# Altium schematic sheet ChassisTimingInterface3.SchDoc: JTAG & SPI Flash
size B; DocumentNumber: 4; Revision: C; SheetNumber: 3; SheetTotal: 12
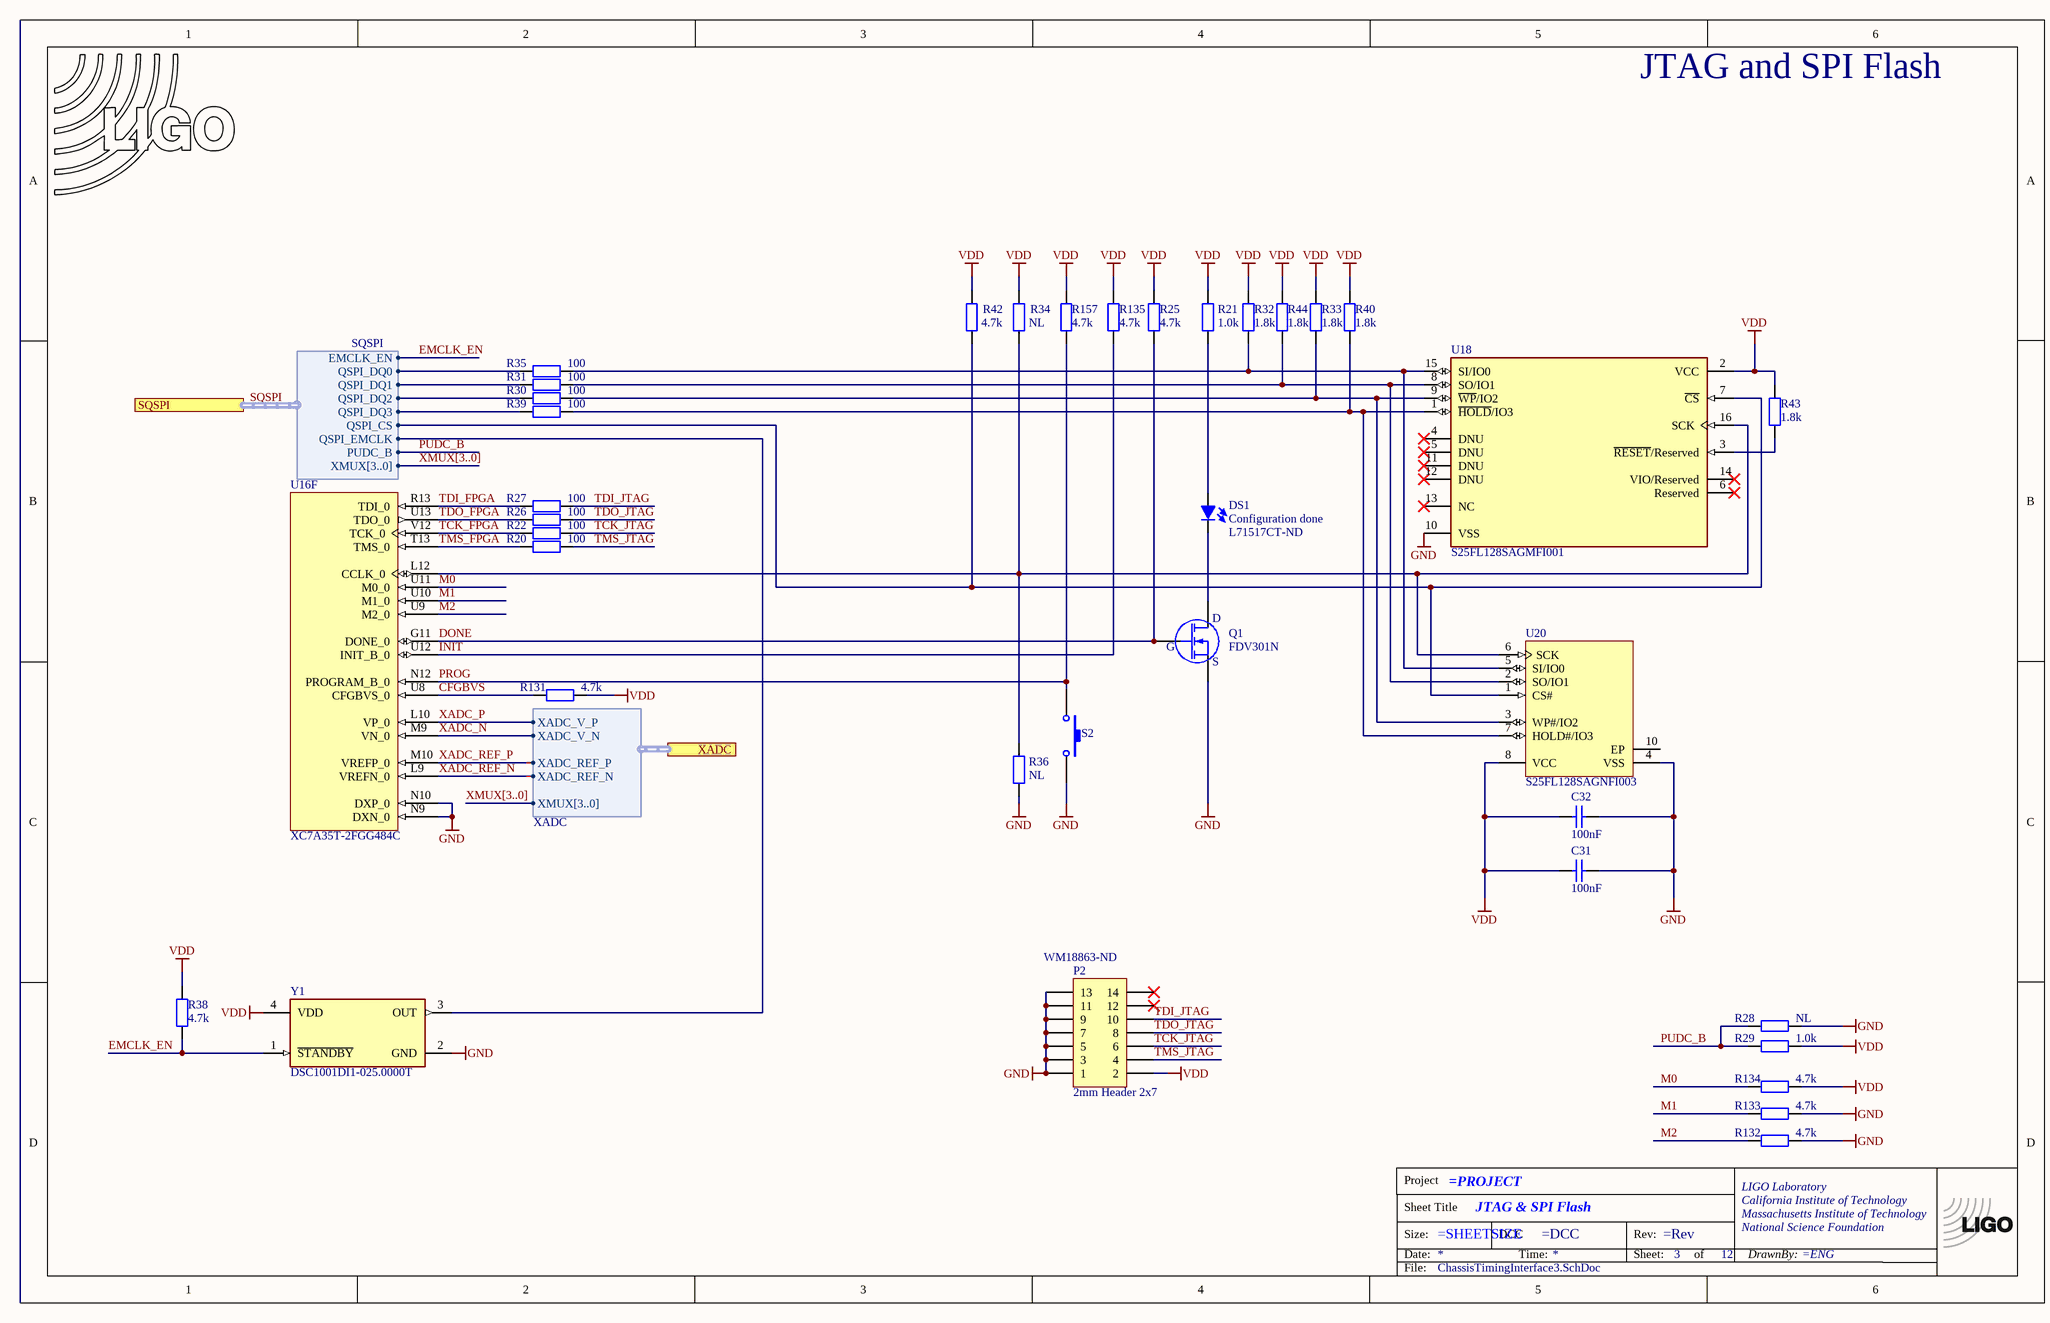
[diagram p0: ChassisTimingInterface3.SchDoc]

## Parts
*?  TitleBlock  (value not drawn)  (graphical)
C31  100nF  [CC1005-0402]
C32  100nF  [CC1005-0402]
DS1  Supplier Part Number 1: L71517CT-ND  [LED-0805]  (hidden comment: LED)
LOGO3  LIGO logo  [LIGO_LOGO]  (value not drawn)  (graphical)
P2  2mm Header 2x7  Supplier Part Number 1: WM18863-ND  [2MM_HDR2X7_RA]
Q1  FDV301N  [SO-G3/C2.25]
R20  100  [CR1608-0603]
R21  1.0k  [CR1608-0603]
R22  100  [CR1608-0603]
R25  4.7k  [CR1005-0402]
R26  100  [CR1608-0603]
R27  100  [CR1608-0603]
R28  NL  [CR1005-0402]
R29  1.0k  [CR1608-0603]
R30  100  [CR1608-0603]
R31  100  [CR1608-0603]
R32  1.8k  [CR1005-0402]
R33  1.8k  [CR1005-0402]
R34  NL  [CR1005-0402]
R35  100  [CR1608-0603]
R36  NL  [CR1005-0402]
R38  4.7k  [CR1005-0402]
R39  100  [CR1608-0603]
R40  1.8k  [CR1005-0402]
R42  4.7k  [CR1005-0402]
R43  1.8k  [CR1005-0402]
R44  1.8k  [CR1005-0402]
R131  4.7k  [CR1005-0402]
R132  4.7k  [CR1005-0402]
R133  4.7k  [CR1005-0402]
R134  4.7k  [CR1005-0402]
R135  4.7k  [CR1005-0402]
R157  4.7k  [CR1005-0402]
S2  B3SN-3112P  [SW_SMD_6MM]  (value not drawn)
U16  XC7A35T-2FGG484C  [FGG484]  (part F of 12)
U18  S25FL128SAGMFI001  [FP-002-15547-MFG]
U20  S25FL128SAGNFI003  [SPSN-WSON-8_L]
Y1  DSC1001DI1-025.0000T  [FP-CDFN2520-4LD-PL-1-MFG]

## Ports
SQSPI (harness SQSPI), XADC (harness XADC)

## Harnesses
SQSPI: QSPI_DQ0, QSPI_DQ1, QSPI_DQ2, QSPI_DQ3, QSPI_CS, QSPI_EMCLK, PUDC_B, XMUX[3..0], EMCLK_EN
XADC: XADC_REF_P, XADC_V_N, XADC_V_P, XMUX[3..0], XADC_REF_N

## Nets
GND: C31.1 C32.1 P2.1 P2.3 P2.5 P2.7 P2.9 P2.11 P2.13 Q1.2(S) R28.2 R36.2 R132.2 R133.2 S2.3 S2.5 U16.N9(DXN_0) U16.N10(DXP_0) U18.10(VSS) U20.4(VSS) Y1.2(GND)
VDD: C31.2 C32.2 P2.2 R21.1 R25.2 R29.2 R32.2 R33.2 R34.1 R38.1 R40.2 R42.1 R43.2 R44.2 R131.2 R134.2 R135.2 R157.2 U18.2(VCC) U20.8(VCC) Y1.4(VDD)
CFGBVS: R131.1 U16.U8(CFGBVS_0)
DONE: Q1.1(G) R25.1 U16.G11(DONE_0)
EMCLK_EN: R38.2 Y1.1(~{STANDBY}) ; port SQSPI.EMCLK_EN
INIT: R135.1 U16.U12(INIT_B_0)
M0: R134.1 U16.U11(M0_0)
M1: R133.1 U16.U10(M1_0)
M2: R132.1 U16.U9(M2_0)
PROG: R157.1 S2.1 U16.N12(PROGRAM_B_0)
PUDC_B: R28.1 R29.1 ; port SQSPI.PUDC_B
SQSPI.QSPI_CS: R42.2 U18.7(~{CS}) U20.1(CS#) ; port SQSPI.QSPI_CS
SQSPI.QSPI_DQ0: R35.2 ; port SQSPI.QSPI_DQ0
SQSPI.QSPI_DQ1: R31.2 ; port SQSPI.QSPI_DQ1
SQSPI.QSPI_DQ2: R30.2 ; port SQSPI.QSPI_DQ2
SQSPI.QSPI_DQ3: R39.2 ; port SQSPI.QSPI_DQ3
SQSPI.QSPI_EMCLK: Y1.3(OUT) ; port SQSPI.QSPI_EMCLK
TCK_FPGA: R22.2 U16.V12(TCK_0)
TCK_JTAG: P2.6 R22.1
TDI_FPGA: R27.2 U16.R13(TDI_0)
TDI_JTAG: P2.10 R27.1
TDO_FPGA: R26.2 U16.U13(TDO_0)
TDO_JTAG: P2.8 R26.1
TMS_FPGA: R20.2 U16.T13(TMS_0)
TMS_JTAG: P2.4 R20.1
XADC_N: U16.M9(VN_0) ; port XADC.XADC_V_N
XADC_P: U16.L10(VP_0) ; port XADC.XADC_V_P
XADC_REF_N: U16.L9(VREFN_0) ; port XADC.XADC_REF_N
XADC_REF_P: U16.M10(VREFP_0) ; port XADC.XADC_REF_P
NetDS1_1: DS1.1(K) Q1.3(D)
NetDS1_2: DS1.2(A) R21.2
NetR30_1: R30.1 R33.1 U18.9(~{WP}/IO2) U20.3(WP#/IO2)
NetR31_1: R31.1 R44.1 U18.8(SO/IO1) U20.2(SO/IO1)
NetR32_1: R32.1 R35.1 U18.15(SI/IO0) U20.5(SI/IO0)
NetR34_2: R34.2 R36.1 U16.L12(CCLK_0) U18.16(SCK) U20.6(SCK)
NetR39_1: R39.1 R40.1 U18.1(~{HOLD}/IO3) U20.7(HOLD#/IO3)
NetR43_1: R43.1 U18.3(~{RESET}/Reserved)

Not connected (* = marked no-connect by the designer): P2 12* 14*; U18 4(DNU)* 5(DNU)* 6(Reserved)* 11(DNU)* 12(DNU)* 13(NC)* 14(VIO/Reserved)*; U20 10(EP)

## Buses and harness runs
bus XMUX[3..0]
harness SQSPI = port SQSPI

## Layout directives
differential pair: XADC_REF_N, XADC_REF_P

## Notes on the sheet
- JTAG and SPI Flash
- (near DS1) Configuration done

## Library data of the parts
C31 C32 = ChipCap: C0402 0.1uF; Part Number: 1276-6720-1-ND; Tolerance: 10%
DS1 = LED: Panel mount LED
LOGO3 = LIGO_logo
P2 = Xilinx_JTAG_Header: Xilinx JTAG header, 7-Pin, Dual row
Q1 = FDV301N: FDV301N, Digital FET, N-channel, SOT23; Part Number: FDV301NCT-ND
R20 R22 R26 R27 R30 R31 R35 R39 = ChipRes1: R0603 100; Part Number: RR08P100DCT-ND; Tolerance: 0.1%
R21 R29 = ChipRes1: R0603 1.0k; Part Number: RR08P1.0KDCT-ND; Tolerance: 0.1%
R25 R38 R42 R131-R135 R157 = ChipRes1: R0402 4.7k; Part Number: RR05P4.7KDCT-ND; Tolerance: 0.1%
R28 R34 R36 = ChipRes1: Resistor, surface mount; Tolerance: 0.1%
R32 R33 R40 R43 R44 = ChipRes1: R0402 1.8k; Part Number: RR05P1.8KDCT-ND; Tolerance: 0.1%
S2 = B3SN-3112P: Switch, SMD, 6mm; Part Number: SW262CT-ND
U16 = CMP-0383-00019-1: Artix-7 FPGA, 250 User I/Os, 4 GTP, 484-Ball BGA, Speed Grade 2, Commercial Grade, Pb-Free
U18 = CMP-12948-000005-1: IC FLASH 128M SPI 133MHZ 16SOIC; Part Number: 1274-1001-ND
U20 = CMP-1329-00027-1: MirrorBit Flash Non-Volatile Memory CMOS 3.0 Volt Core with Versatile I/O, Serial Peripheral Interface with Multi-I/O, 128 Mbit, 133 MHz, -40 to 85 degC, 8-Pin WSON (WNG008), RoHS, Tape and Reel; Part Number: 428-4003-1-ND
Y1 = CMP-06255-000005-1: MEMS OSC XO 25.0000MHZ CMOS SMD; Part Number: 576-4966-5-ND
